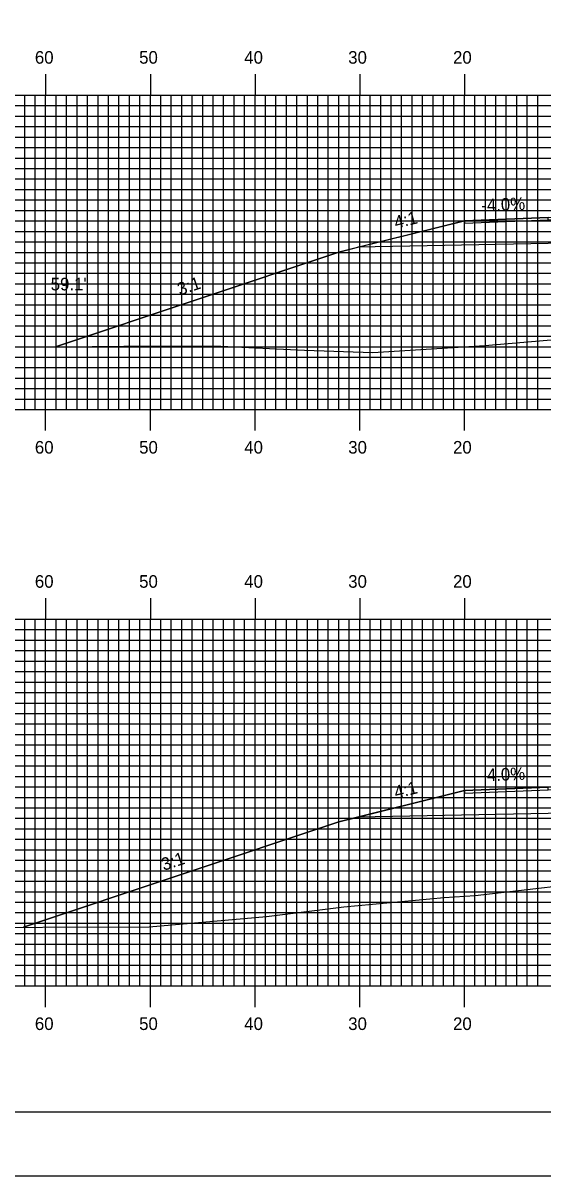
# Model space of a CAD drawing. Extents: x 1818850 to 1819194, y 442591 to 442811.
# Drawn here: x 1818954 to 1819003.7, y 442590.5 to 442700.5 of the extents above; entities that cross this region are included whole.
import ezdxf

# ---------------------------------------------------------------- set-up
doc = ezdxf.new("R2010")
doc.units = 0
for name, color, linetype in [('ANNOTATION', 7, 'Continuous'), ('BORDER', 7, 'Continuous'), ('D_Roadway_Centerline', 7, 'Continuous'), ('D_Roadway_Edge_Shoulder', 7, 'Continuous'), ('D_Roadway_SlopeLines', 7, 'Continuous'), ('D_Roadway_SubGrade', 7, 'Continuous'), ('D_Text_Standard', 7, 'Continuous'), ('H_V ANNOTATION', 7, 'Continuous'), ('MAJOR', 7, 'Continuous'), ('MINOR', 7, 'Continuous'), ('PLOT BOUNDARY', 7, 'Continuous'), ('S_Roadway_Centerline', 7, 'Continuous')]:
    doc.layers.add(name, color=color, linetype=linetype)

msp = doc.modelspace()

# ---------------------------------------------------------------- linework, layer by layer
at = {"layer": 'BORDER'}
msp.add_lwpolyline([(1818866.55, 442596.67), (1819186.55, 442596.67), (1819186.55, 442806.67), (1818866.55, 442806.67)], close=True, dxfattribs=at)
at = {"layer": 'D_Roadway_Centerline'}
for points in [[(1818957.09, 442669.67), (1818984.15, 442678.69), (1818985.98, 442679.15), (1818996.15, 442681.69), (1819004.15, 442682.01), (1819016.15, 442682.25), (1819028.15, 442682.01), (1819036.15, 442681.69), (1819046.33, 442679.15), (1819062.68, 442675.06)], [(1818954.03, 442614.28), (1818984.15, 442624.32), (1818985.98, 442624.77), (1818996.15, 442627.32), (1819004.15, 442627.64), (1819016.15, 442627.88), (1819028.15, 442627.64), (1819036.15, 442627.32), (1819046.33, 442624.77), (1819051.46, 442623.49)]]:
    msp.add_lwpolyline(points, dxfattribs=at)
at = {"layer": 'D_Roadway_Edge_Shoulder'}
for points in [[(1819004.15, 442682.01), (1818996.15, 442681.69), (1818996.15, 442681.44), (1819004.15, 442681.76)], [(1819004.15, 442627.64), (1818996.15, 442627.32), (1818996.15, 442627.07), (1819004.15, 442627.39)]]:
    msp.add_lwpolyline(points, close=True, dxfattribs=at)
at = {"layer": 'D_Roadway_SlopeLines'}
for points in [[(1818996.15, 442681.69), (1818984.15, 442678.69), (1818957.09, 442669.67)], [(1818996.15, 442627.32), (1818984.15, 442624.32), (1818954.03, 442614.28)]]:
    msp.add_lwpolyline(points, dxfattribs=at)
at = {"layer": 'D_Roadway_SubGrade'}
for points in [[(1819004.15, 442679.51), (1818985.98, 442679.15), (1818996.15, 442681.69), (1818996.15, 442681.44), (1819004.15, 442681.76), (1819016.15, 442682), (1819028.15, 442681.76), (1819036.15, 442681.44), (1819036.15, 442681.69), (1819046.33, 442679.15), (1819028.15, 442679.51), (1819016.15, 442679.75)], [(1819004.15, 442625.14), (1818985.98, 442624.77), (1818996.15, 442627.32), (1818996.15, 442627.07), (1819004.15, 442627.39), (1819016.15, 442627.63), (1819028.15, 442627.39), (1819036.15, 442627.07), (1819036.15, 442627.32), (1819046.33, 442624.77), (1819028.15, 442625.14), (1819016.15, 442625.38)]]:
    msp.add_lwpolyline(points, close=True, dxfattribs=at)
at = {"layer": 'MAJOR'}
for p, q in [((1818956.15, 442695.67), (1818956.15, 442693.67)), ((1818966.15, 442695.67), (1818966.15, 442693.67)), ((1818976.15, 442695.67), (1818976.15, 442693.67)), ((1818986.15, 442695.67), (1818986.15, 442693.67)), ((1818996.15, 442695.67), (1818996.15, 442693.67)), ((1818876.15, 442693.67), (1819156.15, 442693.67)), ((1818876.15, 442693.67), (1819156.15, 442693.67)), ((1818956.15, 442663.67), (1818956.15, 442693.67)), ((1818966.15, 442663.67), (1818966.15, 442693.67)), ((1818976.15, 442663.67), (1818976.15, 442693.67)), ((1818986.15, 442663.67), (1818986.15, 442693.67)), ((1818996.15, 442663.67), (1818996.15, 442693.67)), ((1818876.15, 442688.67), (1819156.15, 442688.67)), ((1818876.15, 442683.67), (1819156.15, 442683.67)), ((1818876.15, 442678.67), (1819156.15, 442678.67)), ((1818876.15, 442673.67), (1819156.15, 442673.67)), ((1818876.15, 442668.67), (1819156.15, 442668.67)), ((1818876.15, 442663.67), (1819156.15, 442663.67)), ((1818876.15, 442663.67), (1819156.15, 442663.67)), ((1818956.15, 442661.66), (1818956.15, 442663.67)), ((1818966.15, 442661.66), (1818966.15, 442663.67)), ((1818976.15, 442661.66), (1818976.15, 442663.67)), ((1818986.15, 442661.66), (1818986.15, 442663.67)), ((1818996.15, 442661.66), (1818996.15, 442663.67)), ((1818956.15, 442645.67), (1818956.15, 442643.67)), ((1818966.15, 442645.67), (1818966.15, 442643.67)), ((1818976.15, 442645.67), (1818976.15, 442643.67)), ((1818986.15, 442645.67), (1818986.15, 442643.67)), ((1818996.15, 442645.67), (1818996.15, 442643.67)), ((1818876.15, 442643.67), (1819156.15, 442643.67)), ((1818876.15, 442643.67), (1819156.15, 442643.67)), ((1818956.15, 442608.67), (1818956.15, 442643.67)), ((1818966.15, 442608.67), (1818966.15, 442643.67)), ((1818976.15, 442608.67), (1818976.15, 442643.67)), ((1818986.15, 442608.67), (1818986.15, 442643.67)), ((1818996.15, 442608.67), (1818996.15, 442643.67)), ((1818876.15, 442638.67), (1819156.15, 442638.67)), ((1818876.15, 442633.67), (1819156.15, 442633.67)), ((1818876.15, 442628.67), (1819156.15, 442628.67)), ((1818876.15, 442623.67), (1819156.15, 442623.67)), ((1818876.15, 442618.67), (1819156.15, 442618.67)), ((1818876.15, 442613.67), (1819156.15, 442613.67)), ((1818876.15, 442608.67), (1819156.15, 442608.67)), ((1818876.15, 442608.67), (1819156.15, 442608.67)), ((1818956.15, 442606.66), (1818956.15, 442608.67)), ((1818966.15, 442606.66), (1818966.15, 442608.67)), ((1818976.15, 442606.66), (1818976.15, 442608.67)), ((1818986.15, 442606.66), (1818986.15, 442608.67)), ((1818996.15, 442606.66), (1818996.15, 442608.67))]:
    msp.add_line(p, q, dxfattribs=at)
at = {"layer": 'MINOR'}
for p, q in [((1818954.15, 442663.67), (1818954.15, 442693.67)), ((1818955.15, 442663.67), (1818955.15, 442693.67)), ((1818957.15, 442663.67), (1818957.15, 442693.67)), ((1818958.15, 442663.67), (1818958.15, 442693.67)), ((1818959.15, 442663.67), (1818959.15, 442693.67)), ((1818960.15, 442663.67), (1818960.15, 442693.67)), ((1818961.15, 442663.67), (1818961.15, 442693.67)), ((1818962.15, 442663.67), (1818962.15, 442693.67)), ((1818963.15, 442663.67), (1818963.15, 442693.67)), ((1818964.15, 442663.67), (1818964.15, 442693.67)), ((1818965.15, 442663.67), (1818965.15, 442693.67)), ((1818967.15, 442663.67), (1818967.15, 442693.67)), ((1818968.15, 442663.67), (1818968.15, 442693.67)), ((1818969.15, 442663.67), (1818969.15, 442693.67)), ((1818970.15, 442663.67), (1818970.15, 442693.67)), ((1818971.15, 442663.67), (1818971.15, 442693.67)), ((1818972.15, 442663.67), (1818972.15, 442693.67)), ((1818973.15, 442663.67), (1818973.15, 442693.67)), ((1818974.15, 442663.67), (1818974.15, 442693.67)), ((1818975.15, 442663.67), (1818975.15, 442693.67)), ((1818977.15, 442663.67), (1818977.15, 442693.67)), ((1818978.15, 442663.67), (1818978.15, 442693.67)), ((1818979.15, 442663.67), (1818979.15, 442693.67)), ((1818980.15, 442663.67), (1818980.15, 442693.67)), ((1818981.15, 442663.67), (1818981.15, 442693.67)), ((1818982.15, 442663.67), (1818982.15, 442693.67)), ((1818983.15, 442663.67), (1818983.15, 442693.67)), ((1818984.15, 442663.67), (1818984.15, 442693.67)), ((1818985.15, 442663.67), (1818985.15, 442693.67)), ((1818987.15, 442663.67), (1818987.15, 442693.67)), ((1818988.15, 442663.67), (1818988.15, 442693.67)), ((1818989.15, 442663.67), (1818989.15, 442693.67)), ((1818990.15, 442663.67), (1818990.15, 442693.67)), ((1818991.15, 442663.67), (1818991.15, 442693.67)), ((1818992.15, 442663.67), (1818992.15, 442693.67)), ((1818993.15, 442663.67), (1818993.15, 442693.67)), ((1818994.15, 442663.67), (1818994.15, 442693.67)), ((1818995.15, 442663.67), (1818995.15, 442693.67)), ((1818997.15, 442663.67), (1818997.15, 442693.67)), ((1818998.15, 442663.67), (1818998.15, 442693.67)), ((1818999.15, 442663.67), (1818999.15, 442693.67)), ((1819000.15, 442663.67), (1819000.15, 442693.67)), ((1819001.15, 442663.67), (1819001.15, 442693.67)), ((1819002.15, 442663.67), (1819002.15, 442693.67)), ((1819003.15, 442663.67), (1819003.15, 442693.67)), ((1818876.15, 442692.67), (1819156.15, 442692.67)), ((1818876.15, 442691.67), (1819156.15, 442691.67)), ((1818876.15, 442690.67), (1819156.15, 442690.67)), ((1818876.15, 442689.67), (1819156.15, 442689.67)), ((1818876.15, 442687.67), (1819156.15, 442687.67)), ((1818876.15, 442686.67), (1819156.15, 442686.67)), ((1818876.15, 442685.67), (1819156.15, 442685.67)), ((1818876.15, 442684.67), (1819156.15, 442684.67)), ((1818876.15, 442682.67), (1819156.15, 442682.67)), ((1818876.15, 442681.67), (1819156.15, 442681.67)), ((1818876.15, 442680.67), (1819156.15, 442680.67)), ((1818876.15, 442679.67), (1819156.15, 442679.67)), ((1818876.15, 442677.67), (1819156.15, 442677.67)), ((1818876.15, 442676.67), (1819156.15, 442676.67)), ((1818876.15, 442675.67), (1819156.15, 442675.67)), ((1818876.15, 442674.67), (1819156.15, 442674.67)), ((1818876.15, 442672.67), (1819156.15, 442672.67)), ((1818876.15, 442671.67), (1819156.15, 442671.67)), ((1818876.15, 442670.67), (1819156.15, 442670.67)), ((1818876.15, 442669.67), (1819156.15, 442669.67)), ((1818876.15, 442667.67), (1819156.15, 442667.67)), ((1818876.15, 442666.67), (1819156.15, 442666.67)), ((1818876.15, 442665.67), (1819156.15, 442665.67)), ((1818876.15, 442664.67), (1819156.15, 442664.67)), ((1818954.15, 442608.67), (1818954.15, 442643.67)), ((1818955.15, 442608.67), (1818955.15, 442643.67)), ((1818957.15, 442608.67), (1818957.15, 442643.67)), ((1818958.15, 442608.67), (1818958.15, 442643.67)), ((1818959.15, 442608.67), (1818959.15, 442643.67)), ((1818960.15, 442608.67), (1818960.15, 442643.67)), ((1818961.15, 442608.67), (1818961.15, 442643.67)), ((1818962.15, 442608.67), (1818962.15, 442643.67)), ((1818963.15, 442608.67), (1818963.15, 442643.67)), ((1818964.15, 442608.67), (1818964.15, 442643.67)), ((1818965.15, 442608.67), (1818965.15, 442643.67)), ((1818967.15, 442608.67), (1818967.15, 442643.67)), ((1818968.15, 442608.67), (1818968.15, 442643.67)), ((1818969.15, 442608.67), (1818969.15, 442643.67)), ((1818970.15, 442608.67), (1818970.15, 442643.67)), ((1818971.15, 442608.67), (1818971.15, 442643.67)), ((1818972.15, 442608.67), (1818972.15, 442643.67)), ((1818973.15, 442608.67), (1818973.15, 442643.67)), ((1818974.15, 442608.67), (1818974.15, 442643.67)), ((1818975.15, 442608.67), (1818975.15, 442643.67)), ((1818977.15, 442608.67), (1818977.15, 442643.67)), ((1818978.15, 442608.67), (1818978.15, 442643.67)), ((1818979.15, 442608.67), (1818979.15, 442643.67)), ((1818980.15, 442608.67), (1818980.15, 442643.67)), ((1818981.15, 442608.67), (1818981.15, 442643.67)), ((1818982.15, 442608.67), (1818982.15, 442643.67)), ((1818983.15, 442608.67), (1818983.15, 442643.67)), ((1818984.15, 442608.67), (1818984.15, 442643.67)), ((1818985.15, 442608.67), (1818985.15, 442643.67)), ((1818987.15, 442608.67), (1818987.15, 442643.67)), ((1818988.15, 442608.67), (1818988.15, 442643.67)), ((1818989.15, 442608.67), (1818989.15, 442643.67)), ((1818990.15, 442608.67), (1818990.15, 442643.67)), ((1818991.15, 442608.67), (1818991.15, 442643.67)), ((1818992.15, 442608.67), (1818992.15, 442643.67)), ((1818993.15, 442608.67), (1818993.15, 442643.67)), ((1818994.15, 442608.67), (1818994.15, 442643.67)), ((1818995.15, 442608.67), (1818995.15, 442643.67)), ((1818997.15, 442608.67), (1818997.15, 442643.67)), ((1818998.15, 442608.67), (1818998.15, 442643.67)), ((1818999.15, 442608.67), (1818999.15, 442643.67)), ((1819000.15, 442608.67), (1819000.15, 442643.67)), ((1819001.15, 442608.67), (1819001.15, 442643.67)), ((1819002.15, 442608.67), (1819002.15, 442643.67)), ((1819003.15, 442608.67), (1819003.15, 442643.67)), ((1818876.15, 442642.67), (1819156.15, 442642.67)), ((1818876.15, 442641.67), (1819156.15, 442641.67)), ((1818876.15, 442640.67), (1819156.15, 442640.67)), ((1818876.15, 442639.67), (1819156.15, 442639.67)), ((1818876.15, 442637.67), (1819156.15, 442637.67)), ((1818876.15, 442636.67), (1819156.15, 442636.67)), ((1818876.15, 442635.67), (1819156.15, 442635.67)), ((1818876.15, 442634.67), (1819156.15, 442634.67)), ((1818876.15, 442632.67), (1819156.15, 442632.67)), ((1818876.15, 442631.67), (1819156.15, 442631.67)), ((1818876.15, 442630.67), (1819156.15, 442630.67)), ((1818876.15, 442629.67), (1819156.15, 442629.67)), ((1818876.15, 442627.67), (1819156.15, 442627.67)), ((1818876.15, 442626.67), (1819156.15, 442626.67)), ((1818876.15, 442625.67), (1819156.15, 442625.67)), ((1818876.15, 442624.67), (1819156.15, 442624.67)), ((1818876.15, 442622.67), (1819156.15, 442622.67)), ((1818876.15, 442621.67), (1819156.15, 442621.67)), ((1818876.15, 442620.67), (1819156.15, 442620.67)), ((1818876.15, 442619.67), (1819156.15, 442619.67)), ((1818876.15, 442617.67), (1819156.15, 442617.67)), ((1818876.15, 442616.67), (1819156.15, 442616.67)), ((1818876.15, 442615.67), (1819156.15, 442615.67)), ((1818876.15, 442614.67), (1819156.15, 442614.67)), ((1818876.15, 442612.67), (1819156.15, 442612.67)), ((1818876.15, 442611.67), (1819156.15, 442611.67)), ((1818876.15, 442610.67), (1819156.15, 442610.67)), ((1818876.15, 442609.67), (1819156.15, 442609.67))]:
    msp.add_line(p, q, dxfattribs=at)
at = {"layer": 'PLOT BOUNDARY'}
msp.add_lwpolyline([(1818850.36, 442590.55), (1819190.36, 442590.55), (1819190.36, 442810.55), (1818850.36, 442810.55)], close=True, dxfattribs=at)
at = {"layer": 'S_Roadway_Centerline'}
for points in [[(1818876.15, 442670.16), (1818879.81, 442670.23), (1818880.03, 442670.23), (1818909.11, 442670.03), (1818914.93, 442670.06), (1818918.93, 442670.01), (1818929.9, 442669.84), (1818932.68, 442669.8), (1818943.95, 442669.74), (1818957.52, 442669.67), (1818963.63, 442669.73), (1818972.89, 442669.72), (1818980.88, 442669.33), (1818987.41, 442669.1), (1818998.09, 442669.77), (1819006.66, 442670.52), (1819026.49, 442671.35), (1819039.87, 442672.8), (1819045.19, 442673.38), (1819064.86, 442675.27), (1819066.46, 442675.46), (1819066.98, 442675.51), (1819070.78, 442675.98), (1819083.88, 442677.52)], [(1818945.66, 442614.26), (1818966.04, 442614.3), (1818977.23, 442615.31), (1818984.64, 442616.22), (1818994.21, 442617.1), (1818997.18, 442617.31), (1819010.97, 442618.9), (1819020.28, 442619.88), (1819026.94, 442620.43), (1819037.09, 442622.12), (1819045.34, 442623.01), (1819058.49, 442624.04), (1819064.07, 442624.48), (1819079.13, 442626.05)]]:
    msp.add_lwpolyline(points, dxfattribs=at)

# ---------------------------------------------------------------- texts
at = {"layer": 'ANNOTATION'}
for s, rotation, p in [('-4.0%', 2.2906, (1818997.78, 442682.56)), ('4:1', 14.0362, (1818989.6, 442680.92)), ('3:1', 18.4348, (1818968.96, 442674.54)), ('-4.0%', 2.2906, (1818997.78, 442628.18)), ('4:1', 14.0362, (1818989.6, 442626.54)), ('3:1', 18.4348, (1818967.43, 442619.65))]:
    msp.add_text(s, height=1.2, rotation=rotation, dxfattribs=at).set_placement(p)
at = {"layer": 'D_Text_Standard'}
msp.add_text("59.1'", height=1.2, dxfattribs=at).set_placement((1818956.63, 442675.04))
at = {"layer": 'H_V ANNOTATION'}
for s, p in [('60', (1818955.12, 442696.67)), ('50', (1818965.08, 442696.67)), ('40', (1818975.12, 442696.67)), ('30', (1818985.05, 442696.67)), ('20', (1818995.06, 442696.67)), ('60', (1818955.12, 442659.47)), ('50', (1818965.08, 442659.47)), ('40', (1818975.12, 442659.47)), ('30', (1818985.05, 442659.47)), ('20', (1818995.06, 442659.47)), ('60', (1818955.12, 442646.67)), ('50', (1818965.08, 442646.67)), ('40', (1818975.12, 442646.67)), ('30', (1818985.05, 442646.67)), ('20', (1818995.06, 442646.67)), ('60', (1818955.12, 442604.47)), ('50', (1818965.08, 442604.47)), ('40', (1818975.12, 442604.47)), ('30', (1818985.05, 442604.47)), ('20', (1818995.06, 442604.47))]:
    msp.add_text(s, height=1.2, dxfattribs=at).set_placement(p)

doc.saveas('drawing.dxf')
